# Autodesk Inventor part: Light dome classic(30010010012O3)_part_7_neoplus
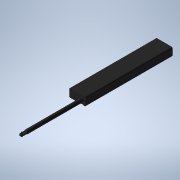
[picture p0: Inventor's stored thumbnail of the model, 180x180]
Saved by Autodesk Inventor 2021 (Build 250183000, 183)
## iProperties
Created: 2026-04
Part Number: Light dome classic(30010010012O3)_part_7_neoplus
Material: Generic
Catalog Web Link: www.3dfindit.com
Description: Light dome classic_part_7_neoplus-
Vendor: KINGSPAN
Document SubType Name: Modeling
Designer: psAdmin
Manufacturer: KINGSPAN
Mass: 1498.71 g
Surface Area: 1404.04 cm^2
Volume: 1498.71 cm^3
Density: 1 g/cm^3
Appearance: PSOLRGB-161-161-161
Category: PARTsolutions
Company: KINGSPAN
Title: Light dome classic(30010010012O3)_part_7_neoplus
Author: Cadenas PARTsolutions
PSOL_IDENT_0: {$CADENAS_DATA/23d-libs/kingspan_kla/light_dome_classic_neoplus/parts/part_7.prj},288 {VTYP=3D},{NB=
PSOL_IDENT_1: Light dome classic(30010010012O3)_part_7_neoplus},{LINA=Light dome classic(30010010012O3)_part_7_neo
PSOL_IDENT_2: plus},{NN=Light dome classic_part_7_neoplus},{DATE=15.07.2024 10:56:16},{GEOMDATE=01.07.2024 07:22:3
PSOL_IDENT_3: 9},{VERSION=},{LINEID=10},{WBVAR=LODLEVEL,L,W,DP,OP,OC,BA},{WBNUMERIC=W}  {NB=Light dome classic(300
PSOL_IDENT_4: 10010012O3)_part_7_neoplus},{LINA=Light dome classic(30010010012O3)_part_7_neoplus},{KT=DUMMY},{IDNR=
PSOL_IDENT_5: },{PN=Light dome classic},{LODLEVEL=300},{L=100},{W=100},{DRIVE=1},{WX=100,150,200,250,300},{DP=1},{
PSOL_IDENT_6: OP=2},{OC=O},{OPX='1','manualy','2','Linear drive 300 mm stroke 24 V and 230 V','3','Linear drive 50
PSOL_IDENT_7: 0 mm stroke 24 V and 230 V','4','Linear drive 750 mm stroke 24 V and 230 V'},{LX=1000},{XWX=1000},{A
PSOL_IDENT_8: NG=9.1637},{EXL=300},{VER=1},{XVERX=2},{BA=3},{DISTXX=27.741}
NB: Light dome classic(30010010012O3)_part_7_neoplus
NN: Light dome classic_part_7_neoplus
NBSYN: $PN.($LODLEVEL.$L.$W.$DP.$OP.$OC.$BA.)_part_7_neoplus
LINA: Light dome classic(30010010012O3)_part_7_neoplus
CATALOG: Light + Air
PN: Light dome classic
LODLEVEL: 300
L: 100
W: 100
DP: Natural ventilation
OP: Linear drive 300 mm stroke 24 V and 230 V
OC: Open
BA: PVC base 50 cm
SUPPLIER: KINGSPAN
ARTICLENO: Light dome classic(30010010012O3)_part_7_neoplus
BOMINFO: Light dome classic(30010010012O3)_part_7_neoplus
CREATOR: CADENAS GmbH
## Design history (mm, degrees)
sketch "Sketch_1"
  geometry: L1 (-63, 16.05)-(-63, -14.95); L2 (-58, -19.95)-(-6.5, -19.95); L3 (-6.5, -19.95)-(-8.5, -17.95); L4 (-8.5, -17.95)-(8.5, -17.95); L5 (8.5, -17.95)-(6.5, -19.95); L6 (6.5, -19.95)-(14.5, -19.95); L7 (19.5, -14.95)-(19.5, -6.5); L8 (19.5, -6.5)-(17.5, -8.5); L9 (17.5, -8.5)-(17.5, 8.5); L10 (17.5, 8.5)-(19.5, 6.5); L11 (19.5, 6.5)-(19.5, 16.05); L12 (14.5, 21.05)-(6.5, 21.05); L13 (6.5, 21.05)-(8.5, 19.05); L14 (8.5, 19.05)-(-8.5, 19.05); L15 (-8.5, 19.05)-(-6.5, 21.05); L16 (-6.5, 21.05)-(-58, 21.05); A1 r 5 centre (-58, -14.95) between (-63, -14.95) and (-58, -19.95); A2 r 5 centre (14.5, -14.95) between (14.5, -19.95) and (19.5, -14.95); A3 r 5 centre (14.5, 16.05) between (19.5, 16.05) and (14.5, 21.05); A4 r 5 centre (-58, 16.05) between (-58, 21.05) and (-63, 16.05)
  constraints: 32 end point, 8 point on circle, 4 centre point
extrude "Extrusion1" join sketch "Sketch_1" distance "d0" = 430; taper "d1" = 0 deg
sketch "Sketch_2"
  geometry: L1 (-63, 16.05)-(-63, -14.95); L2 (-58, -19.95)-(14.5, -19.95); L3 (19.5, -14.95)-(19.5, 16.05); L4 (14.5, 21.05)-(-58, 21.05); A1 r 5 centre (-58, -14.95) between (-63, -14.95) and (-58, -19.95); A2 r 5 centre (14.5, -14.95) between (14.5, -19.95) and (19.5, -14.95); A3 r 5 centre (14.5, 16.05) between (19.5, 16.05) and (14.5, 21.05); A4 r 5 centre (-58, 16.05) between (-58, 21.05) and (-63, 16.05)
  constraints: 8 end point, 8 point on circle, 4 centre point
extrude "Extrusion2" join sketch "Sketch_2" distance "d2" = 3; taper "d3" = 0 deg
sketch "Sketch_3"
  geometry: L1 (0, 308)-(0, 0); L2 (0, 0)-(-9.5, 0); L3 (-9.5, 0)-(-9.5, 275); L4 (-9.5, 275)-(-8, 280); L5 (-8, 280)-(-8, 308); L6 (-8, 308)-(0, 308); L7 (0, 308)-(0, 0)
  constraints: 14 end point
revolve "Revolution1" sketch "Sketch_3" stored, may be unused: angle "d4" = 360 deg
sketch "Sketch_4"
  geometry: L1 (-9.5, 313)-(-9.5, 280); L2 (-9.5, 280)-(-3, 280); L3 (-3, 280)-(-3, 308); L4 (-3, 308)-(3, 308); L5 (3, 308)-(3, 280); L6 (3, 280)-(9.5, 280); L7 (9.5, 280)-(9.5, 313); L8 (9.5, 313)-(-9.5, 313)
  constraints: 16 end point
extrude "Extrusion3" cut sketch "Sketch_4" stored distance "d5" = 40; taper "d6" = 0 deg
sketch "Sketch_5"
  geometry: L1 (9.5, 280)-(9.5, 313); L2 (9.5, 313)-(-9.5, 313); L3 (-9.5, 313)-(-9.5, 280); L4 (-9.5, 280)-(-8, 280); L5 (-8, 280)-(-8, 301.269); L6 (-1.269, 308)-(1.269, 308); L7 (8, 301.269)-(8, 280); L8 (8, 280)-(9.5, 280); A1 r 8.1 centre (0, 300) between (-1.269, 308) and (-8, 301.269); A2 r 8.1 centre (0, 300) between (8, 301.269) and (1.269, 308)
  constraints: 16 end point, 4 point on circle, 2 centre point
extrude "Extrusion4" cut sketch "Sketch_5" stored distance "d7" = 40; taper "d8" = 0 deg
sketch "Sketch_6"
  geometry: C1 r 3.1 at (0, -300); 1 further point
  constraints: 1 centre point
extrude "Extrusion5" join sketch "Sketch_6" distance "d9" = 20; taper "d10" = 0 deg
node "IP_7_XY"
node "IP_7_YZ"
node "IP_7_ZX"
node "IP_7_X"
node "IP_7_Y"
node "IP_7_Z"
node "IP_7_Center"
body "Solid1"
